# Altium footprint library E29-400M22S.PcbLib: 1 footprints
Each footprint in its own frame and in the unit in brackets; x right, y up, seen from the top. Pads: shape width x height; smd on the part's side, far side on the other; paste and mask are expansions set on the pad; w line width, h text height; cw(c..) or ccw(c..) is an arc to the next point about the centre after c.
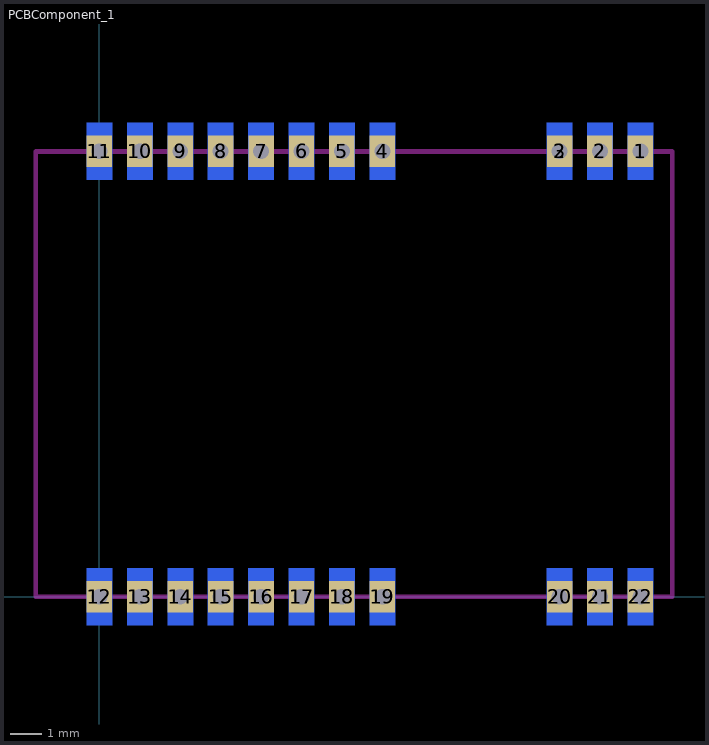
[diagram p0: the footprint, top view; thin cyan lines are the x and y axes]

## PCBComponent_1 [mm]
pads (44):
  rect 0.8x1 hole 0.5: 1(17,14.004) 2(15.73,14.004) 3(14.46,14.004) 4(8.89,14.004) 5(7.62,14.004) 6(6.35,14.004) 7(5.08,14.004) 8(3.81,14.004) 9(2.54,14.004) 10(1.27,14.004) 11(0,14.004) 12(0,0) 13(1.27,0) 14(2.54,0) 15(3.81,0) 16(5.08,0) 17(6.35,0) 18(7.62,0) 19(8.89,0) 20(14.46,0) 21(15.73,0) 22(17,0)
  rect 0.8x1.8 smd far side: 1(17,14.004) 2(14.46,14.004) 2(15.73,14.004) 4(8.89,14.004) 5(7.62,14.004) 6(6.35,14.004) 7(5.08,14.004) 8(3.81,14.004) 9(2.54,14.004) 10(1.27,14.004) 11(0,14.004) 12(0,0) 13(1.27,0) 14(2.54,0) 15(3.81,0) 16(5.08,0) 17(6.35,0) 18(7.62,0) 19(8.89,0) 20(14.46,0) 21(15.73,0) 22(17,0)
Keep-Out Layer:
  lines w0.152: -2,0 -2,14 18,14 18,0 -2,0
